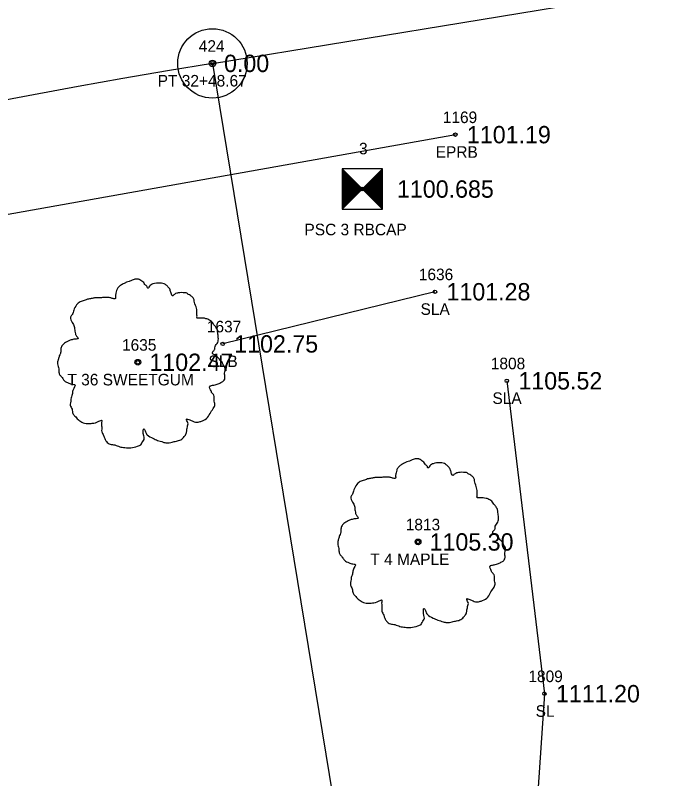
# Model space of a CAD drawing. Extents: x 1539151 to 1541799, y 1198646 to 1201165.
# Drawn here: x 1541211.9 to 1541267.5, y 1200361.6 to 1200427.6 of the extents above; entities that cross this region are included whole.
import ezdxf

# ---------------------------------------------------------------- set-up
doc = ezdxf.new("R2010")
doc.units = 0
for name, color, linetype in [('RD_EX_Road', 7, 'Continuous'), ('RD_EX_Road_txCode', 7, 'Continuous'), ('RD_EX_TX_Road_ELEV', 7, 'Continuous'), ('RD_EX_TX_VEG_ELEV', 7, 'Continuous'), ('RD_EX_VEG', 7, 'Continuous'), ('RD_EX_VEG_txCode', 7, 'Continuous'), ('RD_HC_Cl', 7, 'Continuous'), ('RD_HC_Data', 7, 'Continuous'), ('RD_HC_Survey', 7, 'Continuous'), ('RD_HC_Survey_ELEV', 7, 'Continuous'), ('RD_HC_txCode', 7, 'Continuous'), ('RD_SMD_Locator', 7, 'Continuous')]:
    doc.layers.add(name, color=color, linetype=linetype)

msp = doc.modelspace()

# ---------------------------------------------------------------- linework, layer by layer
at = {"layer": 'RD_EX_Road'}
msp.add_lwpolyline([(1540718.68, 1200081.327), (1540762.243, 1200130.195), (1540779.722, 1200149.92), (1540818.991, 1200193.085), (1540844.694, 1200219.089), (1540861.587, 1200235.219), (1540891.57, 1200261.374), (1540930.279, 1200290.778), (1540971.824, 1200318.199), (1541015.093, 1200342.794), (1541060.357, 1200364.795), (1541076.533, 1200371.562), (1541099.096, 1200380.088), (1541153.211, 1200396.862), (1541201.214, 1200408.644), (1541249.91, 1200417.319)], dxfattribs=at)
at = {"layer": 'RD_EX_VEG'}
msp.add_line((1541248.145, 1200403.736), (1541229.8, 1200399.225), dxfattribs=at)
msp.add_lwpolyline([(1541254.359, 1200396.034), (1541257.607, 1200368.984), (1541256.245, 1200348.581), (1541239.245, 1200317.15), (1541214.687, 1200340.422), (1541208.951, 1200355.573)], dxfattribs=at)
for centre, radius in [((1541222.467, 1200397.639), 0.25), ((1541222.454, 1200397.62), 0.0001), ((1541246.684, 1200382.104), 0.25), ((1541246.671, 1200382.085), 0.0001)]:
    msp.add_circle(centre, radius, dxfattribs=at)
for points in [[(1541222.599, 1200404.806), (1541222.299, 1200404.831), (1541221.974, 1200404.731), (1541221.724, 1200404.631), (1541221.499, 1200404.556), (1541221.274, 1200404.456), (1541220.974, 1200404.281), (1541220.749, 1200404.081), (1541220.624, 1200403.831), (1541220.574, 1200403.606), (1541220.524, 1200403.331), (1541220.524, 1200403.156), (1541220.4, 1200403.131), (1541220.25, 1200403.156), (1541220, 1200403.231), (1541219.75, 1200403.231), (1541219.5, 1200403.231), (1541219.15, 1200403.206), (1541218.8, 1200403.206), (1541218.525, 1200403.156), (1541218.2, 1200403.106), (1541217.826, 1200402.982), (1541217.476, 1200402.857), (1541217.176, 1200402.607), (1541216.926, 1200402.132), (1541216.801, 1200401.782), (1541216.651, 1200401.532), (1541216.801, 1200401.082), (1541216.976, 1200400.732), (1541217.001, 1200400.533), (1541217.076, 1200400.108), (1541217.176, 1200399.883), (1541217.301, 1200399.683), (1541217.226, 1200399.658), (1541216.851, 1200399.608), (1541216.551, 1200399.508), (1541216.126, 1200399.283), (1541215.901, 1200399.058), (1541215.801, 1200398.733), (1541215.777, 1200398.383), (1541215.677, 1200398.184), (1541215.602, 1200397.909), (1541215.577, 1200397.834), (1541215.527, 1200397.509), (1541215.627, 1200397.059), (1541215.652, 1200396.709), (1541215.777, 1200396.484), (1541215.926, 1200396.309), (1541216.101, 1200396.06), (1541216.501, 1200395.835), (1541216.826, 1200395.735), (1541217.026, 1200395.71), (1541216.851, 1200395.21), (1541216.801, 1200394.86), (1541216.676, 1200394.46), (1541216.676, 1200394.385), (1541216.626, 1200393.91), (1541216.776, 1200393.586), (1541216.851, 1200393.211), (1541217.026, 1200392.986), (1541217.301, 1200392.686), (1541217.626, 1200392.461), (1541218.126, 1200392.336), (1541218.525, 1200392.361), (1541219.1, 1200392.536), (1541219.35, 1200392.611), (1541219.325, 1200392.436), (1541219.35, 1200392.061), (1541219.35, 1200391.637), (1541219.5, 1200391.312), (1541219.6, 1200391.037), (1541219.75, 1200390.787), (1541220.075, 1200390.562), (1541220.474, 1200390.487), (1541220.899, 1200390.337), (1541221.349, 1200390.262), (1541221.849, 1200390.237), (1541222.449, 1200390.387), (1541222.723, 1200390.512), (1541222.823, 1200390.687), (1541223.023, 1200391.062), (1541222.973, 1200391.287), (1541222.998, 1200391.886), (1541223.098, 1200391.711), (1541223.273, 1200391.362), (1541223.773, 1200391.062), (1541224.173, 1200390.887), (1541224.648, 1200390.737), (1541224.948, 1200390.662), (1541225.422, 1200390.737), (1541225.797, 1200390.812), (1541226.172, 1200390.937), (1541226.472, 1200391.212), (1541226.647, 1200391.487), (1541226.697, 1200391.761), (1541226.772, 1200392.136), (1541226.822, 1200392.311)], [(1541226.822, 1200392.311), (1541226.747, 1200392.486), (1541226.697, 1200392.736), (1541226.772, 1200392.711), (1541226.947, 1200392.661), (1541227.222, 1200392.536), (1541227.446, 1200392.461), (1541227.771, 1200392.486), (1541228.046, 1200392.586), (1541228.496, 1200392.861), (1541228.771, 1200393.336), (1541229.046, 1200393.736), (1541229.121, 1200394.06), (1541229.071, 1200394.285), (1541229.046, 1200394.785), (1541228.846, 1200395.035), (1541228.796, 1200395.16), (1541228.696, 1200395.56), (1541228.771, 1200395.61), (1541229.046, 1200395.66), (1541229.421, 1200395.785), (1541229.695, 1200395.91), (1541229.92, 1200396.085), (1541229.995, 1200396.309), (1541229.97, 1200396.709), (1541230.02, 1200397.109), (1541229.945, 1200397.259), (1541229.845, 1200397.409), (1541229.77, 1200397.609), (1541229.62, 1200397.759), (1541229.521, 1200397.909), (1541229.421, 1200398.009), (1541229.296, 1200398.159), (1541229.121, 1200398.284), (1541228.971, 1200398.334), (1541228.921, 1200398.484), (1541229.071, 1200398.683), (1541229.121, 1200398.783), (1541229.146, 1200399.008), (1541229.371, 1200399.358), (1541229.421, 1200399.758), (1541229.371, 1200400.183), (1541229.321, 1200400.458), (1541229.171, 1200400.732), (1541228.971, 1200400.982), (1541228.846, 1200401.157), (1541228.671, 1200401.282), (1541228.346, 1200401.407), (1541228.096, 1200401.457), (1541227.746, 1200401.457), (1541227.546, 1200401.507), (1541227.571, 1200401.557), (1541227.571, 1200401.707), (1541227.571, 1200401.982), (1541227.496, 1200402.432), (1541227.346, 1200402.932), (1541227.346, 1200402.957), (1541227.246, 1200403.206), (1541227.022, 1200403.406), (1541226.847, 1200403.506), (1541226.647, 1200403.631), (1541226.397, 1200403.656), (1541226.097, 1200403.656), (1541225.822, 1200403.606), (1541225.622, 1200403.506), (1541225.447, 1200403.381), (1541225.372, 1200403.531), (1541225.272, 1200403.831), (1541225.222, 1200403.981), (1541225.072, 1200404.156), (1541224.848, 1200404.356), (1541224.398, 1200404.481), (1541223.773, 1200404.406), (1541223.473, 1200404.206), (1541223.323, 1200404.031), (1541223.273, 1200404.156), (1541223.073, 1200404.356), (1541222.973, 1200404.531), (1541222.798, 1200404.656), (1541222.649, 1200404.756), (1541222.549, 1200404.806)], [(1541246.816, 1200389.271), (1541246.516, 1200389.296), (1541246.191, 1200389.196), (1541245.941, 1200389.096), (1541245.716, 1200389.021), (1541245.491, 1200388.921), (1541245.191, 1200388.746), (1541244.966, 1200388.546), (1541244.841, 1200388.296), (1541244.791, 1200388.071), (1541244.742, 1200387.797), (1541244.742, 1200387.622), (1541244.617, 1200387.597), (1541244.467, 1200387.622), (1541244.217, 1200387.697), (1541243.967, 1200387.697), (1541243.717, 1200387.697), (1541243.367, 1200387.672), (1541243.017, 1200387.672), (1541242.742, 1200387.622), (1541242.418, 1200387.572), (1541242.043, 1200387.447), (1541241.693, 1200387.322), (1541241.393, 1200387.072), (1541241.143, 1200386.597), (1541241.018, 1200386.247), (1541240.868, 1200385.997), (1541241.018, 1200385.548), (1541241.193, 1200385.198), (1541241.218, 1200384.998), (1541241.293, 1200384.573), (1541241.393, 1200384.348), (1541241.518, 1200384.148), (1541241.443, 1200384.123), (1541241.068, 1200384.073), (1541240.768, 1200383.973), (1541240.343, 1200383.748), (1541240.119, 1200383.523), (1541240.019, 1200383.199), (1541239.994, 1200382.849), (1541239.894, 1200382.649), (1541239.819, 1200382.374), (1541239.794, 1200382.299), (1541239.744, 1200381.974), (1541239.844, 1200381.524), (1541239.869, 1200381.174), (1541239.994, 1200380.95), (1541240.144, 1200380.775), (1541240.318, 1200380.525), (1541240.718, 1200380.3), (1541241.043, 1200380.2), (1541241.243, 1200380.175), (1541241.068, 1200379.675), (1541241.018, 1200379.325), (1541240.893, 1200378.925), (1541240.893, 1200378.851), (1541240.843, 1200378.376), (1541240.993, 1200378.051), (1541241.068, 1200377.676), (1541241.243, 1200377.451), (1541241.518, 1200377.151), (1541241.843, 1200376.926), (1541242.343, 1200376.801), (1541242.742, 1200376.826), (1541243.317, 1200377.001), (1541243.567, 1200377.076), (1541243.542, 1200376.901), (1541243.567, 1200376.526), (1541243.567, 1200376.102), (1541243.717, 1200375.777), (1541243.817, 1200375.502), (1541243.967, 1200375.252), (1541244.292, 1200375.027), (1541244.692, 1200374.952), (1541245.116, 1200374.802), (1541245.566, 1200374.727), (1541246.066, 1200374.702), (1541246.666, 1200374.852), (1541246.941, 1200374.977), (1541247.041, 1200375.152), (1541247.24, 1200375.527), (1541247.19, 1200375.752), (1541247.215, 1200376.352), (1541247.315, 1200376.177), (1541247.49, 1200375.827), (1541247.99, 1200375.527), (1541248.39, 1200375.352), (1541248.865, 1200375.202), (1541249.165, 1200375.127), (1541249.639, 1200375.202), (1541250.014, 1200375.277), (1541250.389, 1200375.402), (1541250.689, 1200375.677), (1541250.864, 1200375.952), (1541250.914, 1200376.227), (1541250.989, 1200376.601), (1541251.039, 1200376.776)], [(1541251.039, 1200376.776), (1541250.964, 1200376.951), (1541250.914, 1200377.201), (1541250.989, 1200377.176), (1541251.164, 1200377.126), (1541251.439, 1200377.001), (1541251.664, 1200376.926), (1541251.988, 1200376.951), (1541252.263, 1200377.051), (1541252.713, 1200377.326), (1541252.988, 1200377.801), (1541253.263, 1200378.201), (1541253.338, 1200378.526), (1541253.288, 1200378.751), (1541253.263, 1200379.25), (1541253.063, 1200379.5), (1541253.013, 1200379.625), (1541252.913, 1200380.025), (1541252.988, 1200380.075), (1541253.263, 1200380.125), (1541253.638, 1200380.25), (1541253.913, 1200380.375), (1541254.137, 1200380.55), (1541254.212, 1200380.775), (1541254.187, 1200381.174), (1541254.237, 1200381.574), (1541254.162, 1200381.724), (1541254.062, 1200381.874), (1541253.987, 1200382.074), (1541253.838, 1200382.224), (1541253.738, 1200382.374), (1541253.638, 1200382.474), (1541253.513, 1200382.624), (1541253.338, 1200382.749), (1541253.188, 1200382.799), (1541253.138, 1200382.949), (1541253.288, 1200383.149), (1541253.338, 1200383.249), (1541253.363, 1200383.473), (1541253.588, 1200383.823), (1541253.638, 1200384.223), (1541253.588, 1200384.648), (1541253.538, 1200384.923), (1541253.388, 1200385.198), (1541253.188, 1200385.448), (1541253.063, 1200385.623), (1541252.888, 1200385.747), (1541252.563, 1200385.872), (1541252.313, 1200385.922), (1541251.963, 1200385.922), (1541251.763, 1200385.972), (1541251.788, 1200386.022), (1541251.788, 1200386.172), (1541251.788, 1200386.447), (1541251.713, 1200386.897), (1541251.564, 1200387.397), (1541251.564, 1200387.422), (1541251.464, 1200387.672), (1541251.239, 1200387.872), (1541251.064, 1200387.971), (1541250.864, 1200388.096), (1541250.614, 1200388.121), (1541250.314, 1200388.121), (1541250.039, 1200388.071), (1541249.839, 1200387.971), (1541249.664, 1200387.847), (1541249.589, 1200387.996), (1541249.489, 1200388.296), (1541249.439, 1200388.446), (1541249.29, 1200388.621), (1541249.065, 1200388.821), (1541248.615, 1200388.946), (1541247.99, 1200388.871), (1541247.69, 1200388.671), (1541247.54, 1200388.496), (1541247.49, 1200388.621), (1541247.29, 1200388.821), (1541247.19, 1200388.996), (1541247.016, 1200389.121), (1541246.866, 1200389.221), (1541246.766, 1200389.271)]]:
    msp.add_spline(points, degree=3, dxfattribs=at)
at = {"layer": 'RD_HC_Cl'}
msp.add_line((1541228.915, 1200423.48), (1541327.047, 1200439.572), dxfattribs=at)
msp.add_arc((1541347.273, 1199701.685), 731.435, 99.312315, 138.327529, dxfattribs=at)
at = {"layer": 'RD_HC_Data'}
msp.add_line((1541228.915, 1200423.48), (1541247.679, 1200309.051), dxfattribs=at)
for radius in [3, 0.282]:
    msp.add_circle((1541228.915, 1200423.48), radius, dxfattribs=at)
at = {"layer": 'RD_HC_Survey'}
for p, q in [((1541240.116, 1200414.366), (1541243.616, 1200410.866)), ((1541243.616, 1200414.366), (1541240.116, 1200410.866)), ((1541240.141, 1200414.341), (1541240.141, 1200410.891)), ((1541240.166, 1200414.316), (1541240.166, 1200410.915)), ((1541240.19, 1200414.292), (1541240.19, 1200410.94)), ((1541240.215, 1200414.267), (1541240.215, 1200410.965)), ((1541240.24, 1200414.242), (1541240.24, 1200410.99)), ((1541240.264, 1200414.217), (1541240.264, 1200411.014)), ((1541240.289, 1200414.193), (1541240.289, 1200411.039)), ((1541240.314, 1200414.168), (1541240.314, 1200411.064)), ((1541240.339, 1200414.143), (1541240.339, 1200411.089)), ((1541240.363, 1200414.118), (1541240.363, 1200411.113)), ((1541240.388, 1200414.094), (1541240.388, 1200411.138)), ((1541240.413, 1200414.069), (1541240.413, 1200411.163)), ((1541240.438, 1200414.044), (1541240.438, 1200411.188)), ((1541243.294, 1200414.044), (1541243.294, 1200411.188)), ((1541243.319, 1200414.069), (1541243.319, 1200411.163)), ((1541243.344, 1200414.094), (1541243.344, 1200411.138)), ((1541243.369, 1200414.118), (1541243.369, 1200411.113)), ((1541243.393, 1200414.143), (1541243.393, 1200411.089)), ((1541243.418, 1200414.168), (1541243.418, 1200411.064)), ((1541243.443, 1200414.193), (1541243.443, 1200411.039)), ((1541243.468, 1200414.217), (1541243.468, 1200411.014)), ((1541243.492, 1200414.242), (1541243.492, 1200410.99)), ((1541243.517, 1200414.267), (1541243.517, 1200410.965)), ((1541243.542, 1200414.292), (1541243.542, 1200410.94)), ((1541243.566, 1200414.316), (1541243.566, 1200410.915)), ((1541243.591, 1200414.341), (1541243.591, 1200410.891)), ((1541240.462, 1200414.019), (1541240.462, 1200411.212)), ((1541240.487, 1200413.995), (1541240.487, 1200411.237)), ((1541240.512, 1200413.97), (1541240.512, 1200411.262)), ((1541240.537, 1200413.945), (1541240.537, 1200411.287)), ((1541240.561, 1200413.92), (1541240.561, 1200411.311)), ((1541240.586, 1200413.896), (1541240.586, 1200411.336)), ((1541240.611, 1200413.871), (1541240.611, 1200411.361)), ((1541240.636, 1200413.846), (1541240.636, 1200411.386)), ((1541240.66, 1200413.821), (1541240.66, 1200411.41)), ((1541240.685, 1200413.797), (1541240.685, 1200411.435)), ((1541240.71, 1200413.772), (1541240.71, 1200411.46)), ((1541240.735, 1200413.747), (1541240.735, 1200411.485)), ((1541240.759, 1200413.722), (1541240.759, 1200411.509)), ((1541240.784, 1200413.698), (1541240.784, 1200411.534)), ((1541240.809, 1200413.673), (1541240.809, 1200411.559)), ((1541240.834, 1200413.648), (1541240.834, 1200411.584)), ((1541240.858, 1200413.623), (1541240.858, 1200411.608)), ((1541240.883, 1200413.599), (1541240.883, 1200411.633)), ((1541240.908, 1200413.574), (1541240.908, 1200411.658)), ((1541240.933, 1200413.549), (1541240.933, 1200411.683)), ((1541240.957, 1200413.524), (1541240.957, 1200411.707)), ((1541240.982, 1200413.5), (1541240.982, 1200411.732)), ((1541241.007, 1200413.475), (1541241.007, 1200411.757)), ((1541241.032, 1200413.45), (1541241.032, 1200411.782)), ((1541241.056, 1200413.425), (1541241.056, 1200411.806)), ((1541241.081, 1200413.401), (1541241.081, 1200411.831)), ((1541242.651, 1200413.401), (1541242.651, 1200411.831)), ((1541242.676, 1200413.425), (1541242.676, 1200411.806)), ((1541242.7, 1200413.45), (1541242.7, 1200411.782)), ((1541242.725, 1200413.475), (1541242.725, 1200411.757)), ((1541242.75, 1200413.5), (1541242.75, 1200411.732)), ((1541242.775, 1200413.524), (1541242.775, 1200411.707)), ((1541242.799, 1200413.549), (1541242.799, 1200411.683)), ((1541242.824, 1200413.574), (1541242.824, 1200411.658)), ((1541242.849, 1200413.599), (1541242.849, 1200411.633)), ((1541242.874, 1200413.623), (1541242.874, 1200411.608)), ((1541242.898, 1200413.648), (1541242.898, 1200411.584)), ((1541242.923, 1200413.673), (1541242.923, 1200411.559)), ((1541242.948, 1200413.698), (1541242.948, 1200411.534)), ((1541242.973, 1200413.722), (1541242.973, 1200411.509)), ((1541242.997, 1200413.747), (1541242.997, 1200411.485)), ((1541243.022, 1200413.772), (1541243.022, 1200411.46)), ((1541243.047, 1200413.797), (1541243.047, 1200411.435)), ((1541243.072, 1200413.821), (1541243.072, 1200411.41)), ((1541243.096, 1200413.846), (1541243.096, 1200411.386)), ((1541243.121, 1200413.871), (1541243.121, 1200411.361)), ((1541243.146, 1200413.896), (1541243.146, 1200411.336)), ((1541243.171, 1200413.92), (1541243.171, 1200411.311)), ((1541243.195, 1200413.945), (1541243.195, 1200411.287)), ((1541243.22, 1200413.97), (1541243.22, 1200411.262)), ((1541243.245, 1200413.995), (1541243.245, 1200411.237)), ((1541243.27, 1200414.019), (1541243.27, 1200411.212)), ((1541241.106, 1200413.376), (1541241.106, 1200411.856)), ((1541241.131, 1200413.351), (1541241.131, 1200411.881)), ((1541241.155, 1200413.326), (1541241.155, 1200411.905)), ((1541241.18, 1200413.302), (1541241.18, 1200411.93)), ((1541241.205, 1200413.277), (1541241.205, 1200411.955)), ((1541241.23, 1200413.252), (1541241.23, 1200411.979)), ((1541241.254, 1200413.227), (1541241.254, 1200412.004)), ((1541241.279, 1200413.203), (1541241.279, 1200412.029)), ((1541241.304, 1200413.178), (1541241.304, 1200412.054)), ((1541241.329, 1200413.153), (1541241.329, 1200412.078)), ((1541241.353, 1200413.128), (1541241.353, 1200412.103)), ((1541241.378, 1200413.104), (1541241.378, 1200412.128)), ((1541241.403, 1200413.079), (1541241.403, 1200412.153)), ((1541241.428, 1200413.054), (1541241.428, 1200412.177)), ((1541241.452, 1200413.029), (1541241.452, 1200412.202)), ((1541241.477, 1200413.005), (1541241.477, 1200412.227)), ((1541241.502, 1200412.98), (1541241.502, 1200412.252)), ((1541241.527, 1200412.955), (1541241.527, 1200412.276)), ((1541241.551, 1200412.93), (1541241.551, 1200412.301)), ((1541241.576, 1200412.906), (1541241.576, 1200412.326)), ((1541241.601, 1200412.881), (1541241.601, 1200412.351)), ((1541241.626, 1200412.856), (1541241.626, 1200412.375)), ((1541241.65, 1200412.831), (1541241.65, 1200412.4)), ((1541241.675, 1200412.807), (1541241.675, 1200412.425)), ((1541241.7, 1200412.782), (1541241.7, 1200412.45)), ((1541241.725, 1200412.757), (1541241.725, 1200412.474)), ((1541241.749, 1200412.732), (1541241.749, 1200412.499)), ((1541241.983, 1200412.732), (1541241.983, 1200412.499)), ((1541242.007, 1200412.757), (1541242.007, 1200412.474)), ((1541242.032, 1200412.782), (1541242.032, 1200412.45)), ((1541242.057, 1200412.807), (1541242.057, 1200412.425)), ((1541242.082, 1200412.831), (1541242.082, 1200412.4)), ((1541242.106, 1200412.856), (1541242.106, 1200412.375)), ((1541242.131, 1200412.881), (1541242.131, 1200412.351)), ((1541242.156, 1200412.906), (1541242.156, 1200412.326)), ((1541242.181, 1200412.93), (1541242.181, 1200412.301)), ((1541242.205, 1200412.955), (1541242.205, 1200412.276)), ((1541242.23, 1200412.98), (1541242.23, 1200412.252)), ((1541242.255, 1200413.005), (1541242.255, 1200412.227)), ((1541242.28, 1200413.029), (1541242.28, 1200412.202)), ((1541242.304, 1200413.054), (1541242.304, 1200412.177)), ((1541242.329, 1200413.079), (1541242.329, 1200412.153)), ((1541242.354, 1200413.104), (1541242.354, 1200412.128)), ((1541242.379, 1200413.128), (1541242.379, 1200412.103)), ((1541242.403, 1200413.153), (1541242.403, 1200412.078)), ((1541242.428, 1200413.178), (1541242.428, 1200412.054)), ((1541242.453, 1200413.203), (1541242.453, 1200412.029)), ((1541242.478, 1200413.227), (1541242.478, 1200412.004)), ((1541242.502, 1200413.252), (1541242.502, 1200411.979)), ((1541242.527, 1200413.277), (1541242.527, 1200411.955)), ((1541242.552, 1200413.302), (1541242.552, 1200411.93)), ((1541242.577, 1200413.326), (1541242.577, 1200411.905)), ((1541242.601, 1200413.351), (1541242.601, 1200411.881)), ((1541242.626, 1200413.376), (1541242.626, 1200411.856)), ((1541241.774, 1200412.708), (1541241.774, 1200412.524)), ((1541241.799, 1200412.683), (1541241.799, 1200412.549)), ((1541241.824, 1200412.658), (1541241.824, 1200412.573)), ((1541241.848, 1200412.633), (1541241.848, 1200412.598)), ((1541241.884, 1200412.633), (1541241.884, 1200412.598)), ((1541241.908, 1200412.658), (1541241.908, 1200412.573)), ((1541241.933, 1200412.683), (1541241.933, 1200412.549)), ((1541241.958, 1200412.708), (1541241.958, 1200412.524))]:
    msp.add_line(p, q, dxfattribs=at)
msp.add_lwpolyline([(1541243.616, 1200414.366), (1541240.116, 1200414.366), (1541240.116, 1200410.866), (1541243.616, 1200410.866)], close=True, dxfattribs=at)
at = {"layer": 'RD_SMD_Locator'}
for centre in [(1541228.915, 1200423.48), (1541249.91, 1200417.319), (1541241.866, 1200412.616), (1541248.145, 1200403.736), (1541229.8, 1200399.225), (1541222.467, 1200397.638), (1541254.359, 1200396.034), (1541246.684, 1200382.104), (1541257.607, 1200368.984)]:
    msp.add_circle(centre, 0.15, dxfattribs=at)

# ---------------------------------------------------------------- texts
at = {"layer": 'RD_EX_Road_txCode'}
for s, p in [('1169', (1541248.823, 1200418.319)), ('EPRB', (1541248.209, 1200415.319))]:
    msp.add_text(s, height=1, dxfattribs=at).set_placement(p)
at = {"layer": 'RD_EX_TX_Road_ELEV'}
msp.add_text('1101.19', height=1.5, dxfattribs=at).set_placement((1541250.91, 1200416.569))
at = {"layer": 'RD_EX_TX_VEG_ELEV'}
for s, p in [('1101.28', (1541249.145, 1200402.986)), ('1102.75', (1541230.8, 1200398.475)), ('1102.47', (1541223.467, 1200396.888)), ('1105.52', (1541255.359, 1200395.284)), ('1105.30', (1541247.684, 1200381.354)), ('1111.20', (1541258.607, 1200368.234))]:
    msp.add_text(s, height=1.5, dxfattribs=at).set_placement(p)
at = {"layer": 'RD_EX_VEG_txCode'}
for s, p in [('1636', (1541246.751, 1200404.736)), ('SLA', (1541246.901, 1200401.736)), ('1637', (1541228.43, 1200400.225)), ('1635', (1541221.097, 1200398.638)), ('SLB', (1541228.571, 1200397.225)), ('1808', (1541252.973, 1200397.034)), ('T 36 SWEETGUM', (1541216.38, 1200395.638)), ('SLA', (1541253.115, 1200394.034)), ('1813', (1541245.621, 1200383.104)), ('T 4 MAPLE', (1541242.562, 1200380.104)), ('1809', (1541256.221, 1200369.984)), ('SL', (1541256.851, 1200366.984))]:
    msp.add_text(s, height=1, dxfattribs=at).set_placement(p)
at = {"layer": 'RD_HC_Survey_ELEV'}
for s, p in [('0.00', (1541229.915, 1200422.73)), ('1100.685', (1541244.866, 1200411.866))]:
    msp.add_text(s, height=1.5, dxfattribs=at).set_placement(p)
at = {"layer": 'RD_HC_txCode'}
for s, p in [('424', (1541227.734, 1200424.48)), ('PT 32+48.67', (1541224.183, 1200421.48)), ('3', (1541241.583, 1200415.616)), ('PSC 3 RBCAP', (1541236.866, 1200408.616))]:
    msp.add_text(s, height=1, dxfattribs=at).set_placement(p)

doc.saveas('drawing.dxf')
